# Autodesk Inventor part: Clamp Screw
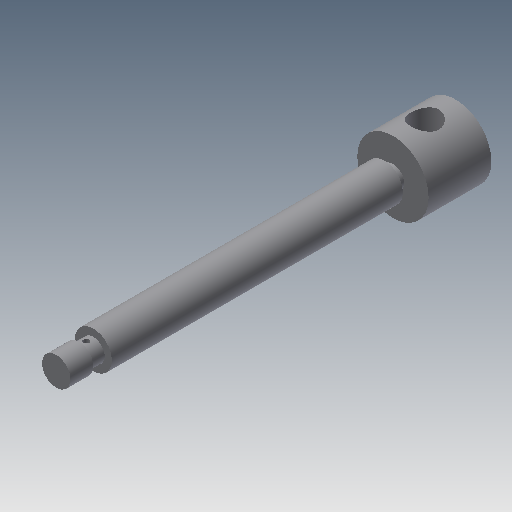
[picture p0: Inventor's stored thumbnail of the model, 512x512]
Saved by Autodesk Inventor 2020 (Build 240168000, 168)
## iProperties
Created: 2002-02
Part Number: Clamp Screw
Document SubType Name: Modeling
Designer: ***
Density: 1 g/cm^3
Material: Generic
Mass: 23.4191 g
Surface Area: 81.8482 cm^2
Volume: 23.4191 cm^3
Appearance: Default
Control State: 0
Master: False
Checked Out: False
Shininess: 77.0
Length Units: 11269
Angle Units: 11279
Time Units: 11290
Mass Units: 11283
Length Display Precision: 3
Angle Display Precision: 2
Density: 0.0
Volumn: 0.0
Area: 0.0
PropertySet Name: Model Information
Author: ***
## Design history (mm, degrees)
sketch "Sketch1"
  geometry: L1 (0, 140)-(5, 140); L2 (5, 140)-(5, 132); L3 (5, 132)-(4, 132); L4 (4, 132)-(4, 127); L5 (4, 127)-(6.5, 127); L6 (6.5, 127)-(6.5, 25); L7 (6.5, 25)-(4, 25); L8 (4, 25)-(4, 22); L9 (4, 22)-(12.5, 22); L10 (12.5, 22)-(12.5, 0); L11 (12.5, 0)-(0, 0); L12 (0, 0)-(0, 140)
  constraints: 24 end point, 10 parallel, 1 horizontal, 1 perpendicular
  dimensions: "d0" = 10 diameter of L2 L12; "d1" = 8 diameter of L4 L12; "d2" = 13 diameter of L6 L12; "d3" = 8 diameter of L7.end L12; "d4" = 25 diameter of L10 L12; "d5" = 3 distance from line of L7.end L9; "d6" = 8 distance of L1.end L2.end; "d7" = 13 vertical distance of L1.end L5.end; "d8" = 22 distance of L9.end L10.end; "d10" = 102 distance of L5.end L6.end
revolve "Revolution1" sketch "Sketch1" stored, may be unused: angle "d11" = 90 deg
sketch "Sketch3"
  geometry: L1 (-12.5, 0)-(12.5, 0) reference; C1 r 5 at (-0.113, 11)
  constraints: 1 centre point
  dimensions: "d13" = 10 diameter of C1; "d14" = 11 distance from line of L1 C1.centre
extrude "Extrusion1" cut sketch "Sketch3" extent not by distance; stored distance "d15" = 10; taper "d16" = 0 deg
sketch "Sketch4"
  geometry: L1 (0, 138.841)-(0, 0); L2 (-12.5, 0)-(12.5, 0) reference; L3 (-5, 140)-(5, 140) reference; C1 r 1 at (0, 129.5)
  constraints: 2 end point, 1 centre point, 1 point on line, 1 vertical
  dimensions: "d17" = 2 diameter of C1; "d18" = 10.5 distance from line of L3 C1.centre
extrude "Extrusion2" cut sketch "Sketch4" stored distance "d19" = 10; taper "d20" = 0 deg
body "Solid1"
